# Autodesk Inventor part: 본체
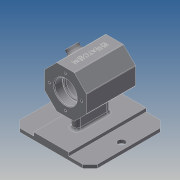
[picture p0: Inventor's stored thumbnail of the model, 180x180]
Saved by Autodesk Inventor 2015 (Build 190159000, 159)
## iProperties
Created: 2018-06
Part Number: 본체
Material: 일반
Document SubType Name: Modeling
Designer: 김영신
Density: 1 g/cm^3
Appearance: 기본값
Author: 김영신
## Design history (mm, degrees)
sketch "스케치1"
  geometry: L1 (-55, 55)-(55, 55); L2 (55, 55)-(55, -55); L3 (55, -55)-(-55, -55); L4 (-55, -55)-(-55, 55); 3 further points
  constraints: 8 end point, 2 midpoint, 2 parallel, 1 horizontal, 1 horizontal alignment, 1 perpendicular, 1 vertical alignment
  dimensions: "d0" = 110 distance between parallel lines of L2 L4; "d1" = 110 distance between parallel lines of L3 L1
extrude "돌출1" new body sketch "스케치1" distance "d2" = 5; taper "d3" = 0 deg
sketch "스케치2"
  geometry: L1 (-25, 55)-(25, 55); L2 (25, 55)-(25, -55); L3 (25, -55)-(-25, -55); L4 (-25, -55)-(-25, 55); L5 (55, 55)-(-55, 55) reference; L6 (55, -55)-(55, 55) reference; L7 (-55, 55)-(-55, -55) reference; 3 further points
  constraints: 8 end point, 2 midpoint, 2 parallel, 1 collinear, 1 horizontal, 1 horizontal alignment, 1 perpendicular, 1 vertical alignment
  dimensions: "d4" = 30 distance between parallel lines of L6 L2; "d5" = 30 distance between parallel lines of L7 L4 (derived)
extrude "돌출2" join sketch "스케치2" distance "d6" = 5; taper "d7" = 0 deg
sketch "스케치4"
  geometry: L1 (30, 74.426)-(30, 49.574); L2 (30, 49.574)-(12.426, 32); L3 (12.426, 32)-(-12.426, 32); L4 (-12.426, 32)-(-30, 49.574); L5 (-30, 49.574)-(-30, 74.426); L6 (-30, 74.426)-(-12.426, 92); L7 (-12.426, 92)-(12.426, 92); L8 (12.426, 92)-(30, 74.426); L9 (0, 62)-(12.426, 92); L10 (0, 62)-(-12.426, 92); L11 (0, 62)-(0, 92); C1 r 30 at (0, 62); 1 further point
  constraints: 22 end point, 2 vertical alignment, 1 centre point, 1 coincident, 1 midpoint, 1 vertical, 17 other
  dimensions: "d10" = 60 diameter of C1; "d11" = 62 distance of point (0, 0) C1.centre; "d12" = 22.5 deg angle of L9 L11 (derived); "d100" = 30 distance from line of C1.centre L5
extrude "돌출3" join sketch "스케치4" stored distance "d14" = 70; taper "d15" = 0 deg
sketch "스케치5"
  geometry: L1 (0, -19)-(0, 19); L2 (5, -19)-(5, 19); L3 (-5, 19)-(-5, -19); A1 r 5 centre (0, -19) between (-5, -19) and (5, -19); A2 r 5 centre (0, 19) between (5, 19) and (-5, 19); 2 further points
  constraints: 8 end point, 4 point on circle, 4 tangent, 2 centre point, 1 coincident, 1 midpoint, 1 parallel, 1 vertical
  dimensions: "d16" = 38 distance of L1.end L1.start; "d17" = 5 radius of A1
extrude "돌출4" join sketch "스케치5" stored distance "d18" = 70; taper "d19" = 0 deg
sketch "스케치8"
  geometry: L1 (-24.853, 70)-(0, 70) reference; C1 r 8 at (-12.426, 35); 2 further points
  constraints: 1 centre point, 1 horizontal alignment, 1 midpoint, 1 vertical alignment
  dimensions: "d30" = 16 diameter of C1
extrude "돌출5" join sketch "스케치8" distance "d31" = 7; taper "d32" = 0 deg
sketch "스케치9"
  geometry: L1 (-55, -55)-(-55, 55) reference; L2 (55, 55)-(55, -55) reference; C1 r 5 at (45, 0); C2 r 5 at (-45, 0); 1 further point
  constraints: 2 centre point, 2 horizontal alignment
  dimensions: "d33" = 10 diameter of C1; "d34" = 10 diameter of C2; "d35" = 10 distance from line of L1 C2.centre; "d36" = 10 distance from line of L2 C1.centre
extrude "돌출6" cut sketch "스케치9" stored distance "d37" = 7; taper "d38" = 0 deg
sketch "스케치10"
  geometry: L1 (35, 92)-(35, 74.426) reference; L2 (-35, 49.574)-(-35, 74.426) reference; L3 (35, 62)-(-35, 62); L4 (23, 76)-(20, 76); L5 (20, 76)-(20, 84); L6 (17, 87)-(-17, 87); L7 (-20, 84)-(-20, 76); L8 (-20, 76)-(-23, 76); L9 (-23, 76)-(-23, 77.7); L10 (-23.3, 78)-(-35, 78); L11 (-35, 78)-(-35, 62); L12 (35, 62)-(35, 78); L13 (35, 78)-(23.3, 78); L14 (23, 77.7)-(23, 76); A1 r 0.3 centre (23.3, 77.7) between (23.3, 78) and (23, 77.7); A2 r 0.3 centre (-23.3, 77.7) between (-23, 77.7) and (-23.3, 78); A3 r 3 centre (-17, 84) between (-17, 87) and (-20, 84); A4 r 3 centre (17, 84) between (20, 84) and (17, 87); 2 further points
  constraints: 24 end point, 8 perpendicular, 8 point on circle, 8 tangent, 4 centre point, 2 equal radius, 2 midpoint, 1 collinear, 1 horizontal, 1 point on line, 1 vertical alignment
  dimensions: "d39" = 62 distance from line of point (0, 0) L3; "d40" = 32 diameter of L13 L3; "d41" = 28 diameter of L4 L3; "d42" = 50 diameter of L6 L3; "d43" = 28 diameter of L8 L3; "d44" = 32 diameter of L10 L3; "d45" = 12 distance between parallel lines of L1 L14; "d46" = 3 distance between parallel lines of L5 L14; "d47" = 40 distance between parallel lines of L7 L5; "d48" = 3 distance between parallel lines of L9 L7; "d49" = 12 distance between parallel lines of L11 L9 (derived); "d50" = 0.3 radius of A1; "d51" = 3 radius of A3
revolve "회전1" sketch "스케치10" stored, may be unused: angle "d52" = 90 deg
chamfer "모따기1" distance "d53" = 1; stored, may be unused: second distance "d54" = 2, angle "d55" = 45 deg
sketch "스케치11" dims "d56" = 46
  geometry: C1 r 17 at (0, -62) reference; 3 further points
  constraints: 2 vertical alignment, 1 coincident, 2 other
hole "구멍1" sketch "스케치11" at (0, -85) diameter "d57" = 3.242; stored, may be unused: countersink angle "d61" = 90 deg, drill point angle "d63" = 118 deg; dims "d58" = 8, "d59" = 4, "d60" = 2, "d62" = 10
sketch "스케치12" dims "d67" = 46
  geometry: C1 r 17 at (0, 62) reference; 3 further points
  constraints: 2 vertical alignment, 1 coincident, 2 other
hole "구멍2" sketch "스케치12" at (0, 85) diameter "d68" = 3.242; stored, may be unused: countersink angle "d72" = 90 deg, drill point angle "d74" = 118 deg; dims "d69" = 8, "d70" = 4, "d71" = 2, "d73" = 10
hole "구멍3" diameter "d80" = 8; stored, may be unused: countersink angle "d84" = 90 deg, drill point angle "d86" = 118 deg; dims "d78" = 10, "d79" = 10, "d81" = 8, "d82" = 4, "d83" = 2, "d85" = 30
chamfer "모따기2" distance "d87" = 1; stored, may be unused: second distance "d88" = 2, angle "d89" = 45 deg
chamfer "모따기3" distance "d90" = 10; stored, may be unused: second distance "d91" = 2, angle "d92" = 45 deg
sketch "스케치13"
  geometry: L1 (0, 0)-(24.853, 0) reference; 2 further points
  constraints: 1 coincident, 1 other
  dimensions: "d93" = 35 distance from line of L1 point (12.426, -35)
feature "엠보싱1" sketch "스케치13" dims "d0" = 110, "d1" = 110, "d10" = 60, "d11" = 62, "d12" = 22.5 deg (derived), "d94" = 0.5, "d95" = 0, "d100" = 30
fillet "모깎기1" dims "d96" = 3
fillet "모깎기2" dims "d97" = 3
fillet "모깎기3" dims "d98" = 1
node "솔리드1"
pattern_circular "원형 패턴1" dims angle "d65" = 360 deg
pattern_circular "원형 패턴2" dims angle "d76" = 360 deg
